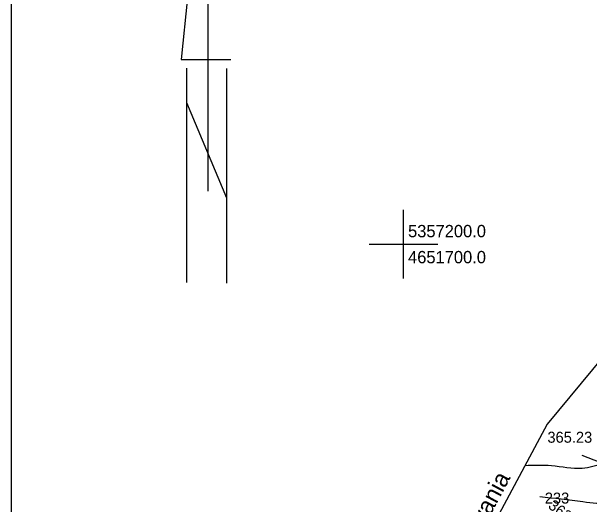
# Model space of a CAD drawing. Extents: x 4635329 to 4651863, y 5356628 to 5367582.
# Drawn here: x 4651671.38 to 4651713.58, y 5357181 to 5357216.98 of the extents above; entities that cross this region are included whole.
import ezdxf

# ---------------------------------------------------------------- set-up
doc = ezdxf.new("R2010")
doc.units = 0
for name, color, linetype in [('Level 1', 7, 'Continuous'), ('Level 13', 7, 'Continuous'), ('Level 20', 7, 'Continuous'), ('Level 45', 7, 'Continuous'), ('Level 46', 7, 'Continuous'), ('Level 58', 7, 'Continuous'), ('Level 6', 7, 'Continuous'), ('Level 60', 7, 'Continuous'), ('Level 63', 7, 'Continuous')]:
    doc.layers.add(name, color=color, linetype=linetype)

msp = doc.modelspace()

# ---------------------------------------------------------------- linework, layer by layer
at = {"layer": 'Level 1'}
for p, q in [((4651738.209, 5357220.297), (4651710.481, 5357186.845)), ((4651710.481, 5357186.845), (4651700.061, 5357167.337))]:
    msp.add_line(p, q, dxfattribs=at)
at = {"layer": 'Level 13'}
for p, q in [((4651685.72, 5357232.923), (4651683.775, 5357213.465)), ((4651685.72, 5357232.923), (4651685.72, 5357203.858)), ((4651683.775, 5357213.465), (4651687.385, 5357213.479)), ((4651684.157, 5357212.847), (4651684.157, 5357197.196)), ((4651687.084, 5357212.809), (4651687.084, 5357197.158)), ((4651684.157, 5357210.33), (4651687.084, 5357203.378))]:
    msp.add_line(p, q, dxfattribs=at)
msp.add_lwpolyline([(4651671.382, 5357244.835), (4651857.008, 5357244.835), (4651857.008, 5357005.82), (4651671.382, 5357005.82)], close=True, dxfattribs=at)
at = {"layer": 'Level 20'}
msp.add_lwpolyline([(4651720.492, 5357181.672), (4651713.051, 5357184.577)], dxfattribs=at)
at = {"layer": 'Level 46'}
for points in [[(4651714.604, 5357183.971), (4651713.048, 5357183.63), (4651710.805, 5357183.812), (4651708.867, 5357183.824)], [(4651709.956, 5357181.568), (4651713.109, 5357181.204), (4651715.049, 5357181.144), (4651716.625, 5357181.871), (4651717.759, 5357182.739)]]:
    msp.add_spline(points, degree=3, dxfattribs=at)
at = {"layer": 'Level 60'}
for p, q in [((4651700, 5357197.5), (4651700, 5357202.5)), ((4651697.5, 5357200), (4651702.5, 5357200))]:
    msp.add_line(p, q, dxfattribs=at)

# ---------------------------------------------------------------- texts
at = {"layer": 'Level 45'}
msp.add_text('365.23', height=0.8, dxfattribs=at).set_placement((4651710.511, 5357185.5))
msp.add_text('363.80', height=0.8, rotation=322.7649, dxfattribs=at).set_placement((4651710.5, 5357180.777))
at = {"layer": 'Level 58'}
for s, p in [(' 5357200.0 ', (4651700, 5357200.5)), (' 4651700.0 ', (4651700, 5357198.6))]:
    msp.add_text(s, height=0.9, dxfattribs=at).set_placement(p)
at = {"layer": 'Level 6'}
msp.add_text('Zakres opracowania', height=1.25, rotation=61.8916, dxfattribs=at).set_placement((4651700.748, 5357169.684))
at = {"layer": 'Level 63'}
msp.add_text('233', height=0.8, dxfattribs=at).set_placement((4651710.32, 5357181.06))

doc.saveas('drawing.dxf')
